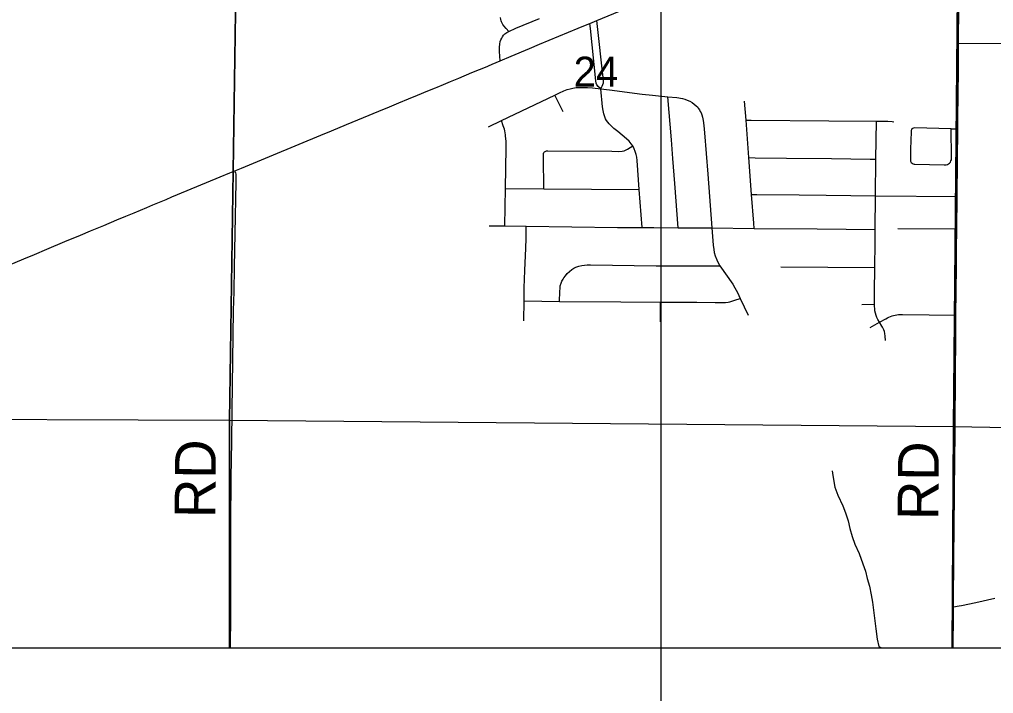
# Model space of a CAD drawing. Extents: x -87 to 2145, y -2128 to 440.
# Drawn here: x -43.13 to -41.77, y -697.486 to -696.545 of the extents above; entities that cross this region are included whole.
import ezdxf

# ---------------------------------------------------------------- set-up
doc = ezdxf.new("R2010")
doc.units = 0
for name, color, linetype in [('GM_X_City_Street', 7, 'Continuous'), ('GM_X_County_Road', 7, 'Continuous'), ('GM_X_County_Road_Text', 7, 'Continuous'), ('GM_X_Minor_River', 7, 'Continuous'), ('GM_X_Section', 7, 'Continuous'), ('GM_X_Section_Text', 7, 'Continuous'), ('GM_X_Township_Road', 7, 'Continuous'), ('GM_X_Township_Road_Text', 7, 'Continuous'), ('GM_X_Township_Text', 7, 'Continuous'), ('SC_Scratch1', 7, 'Continuous'), ('SH_Cut_Line', 7, 'Continuous'), ('SN_P_Text', 7, 'Continuous')]:
    doc.layers.add(name, color=color, linetype=linetype)

msp = doc.modelspace()

# ---------------------------------------------------------------- linework, layer by layer
at = {"layer": 'GM_X_City_Street'}
for p, q in [((-42.3711, -696.6737), (-42.3828, -696.6504)), ((-41.9038, -696.8369), (-41.8215, -696.8373)), ((-42.0671, -696.8902), (-41.9361, -696.8913)), ((-42.2353, -696.9672), (-42.2353, -696.9395)), ((-41.9541, -696.943), (-41.9365, -696.9427))]:
    msp.add_line(p, q, dxfattribs=at)
for points in [[(-42.4589, -696.6025), (-42.4598, -696.5898), (-42.4599, -696.5836), (-42.4597, -696.5793), (-42.4589, -696.5756), (-42.458, -696.5731), (-42.4568, -696.5708), (-42.4558, -696.569), (-42.4543, -696.5669), (-42.4526, -696.5651), (-42.4499, -696.5633), (-42.4471, -696.5617), (-42.4373, -696.5571), (-42.404, -696.5433)], [(-42.4471, -696.5617), (-42.4509, -696.5575), (-42.454, -696.554), (-42.4555, -696.5519), (-42.4564, -696.5501), (-42.4571, -696.5484), (-42.4576, -696.5468), (-42.458, -696.545), (-42.4584, -696.5423)], [(-42.3186, -696.6416), (-42.3167, -696.6382), (-42.3156, -696.6357), (-42.315, -696.6334), (-42.3148, -696.629), (-42.3156, -696.6222), (-42.3233, -696.5549), (-42.3243, -696.5464)], [(-42.3186, -696.6416), (-42.3222, -696.6385), (-42.3242, -696.636), (-42.3251, -696.6339), (-42.3257, -696.6306), (-42.3331, -696.5573), (-42.3338, -696.5504)], [(-41.8194, -696.5782), (-41.7567, -696.5786), (-41.6932, -696.5793), (-41.6298, -696.5803), (-41.5452, -696.581), (-41.4808, -696.5816), (-41.4797, -696.5816), (-41.4131, -696.583), (-41.3978, -696.5833), (-41.319, -696.5825), (-41.3127, -696.5824), (-41.2588, -696.583), (-41.2535, -696.5831), (-41.1875, -696.5837), (-41.1213, -696.5842), (-41.0942, -696.5845), (-41.0122, -696.5851), (-41.0046, -696.5852)], [(-42.4752, -696.6947), (-42.4573, -696.6861), (-42.3828, -696.6504), (-42.3764, -696.6473), (-42.3701, -696.6446), (-42.3654, -696.6429), (-42.3613, -696.6416), (-42.3574, -696.6408), (-42.3528, -696.6401), (-42.3491, -696.6398), (-42.3453, -696.6397), (-42.3372, -696.6397), (-42.3302, -696.6402), (-42.3186, -696.6416), (-42.3066, -696.643), (-42.261, -696.649), (-42.2462, -696.6507), (-42.2248, -696.6527), (-42.2125, -696.654), (-42.2047, -696.6552), (-42.2011, -696.6562), (-42.1981, -696.6574), (-42.1944, -696.6591), (-42.1912, -696.661), (-42.1882, -696.663), (-42.1854, -696.6653), (-42.1837, -696.6671), (-42.1826, -696.6687), (-42.181, -696.671), (-42.1798, -696.6734), (-42.1787, -696.6755), (-42.1776, -696.6781), (-42.1767, -696.6813), (-42.1759, -696.6862), (-42.1749, -696.6931), (-42.1737, -696.7032), (-42.1692, -696.7608), (-42.1634, -696.836), (-42.1616, -696.86), (-42.161, -696.8662), (-42.1602, -696.8705), (-42.1588, -696.8752), (-42.1568, -696.8804), (-42.1544, -696.8855), (-42.1523, -696.8891), (-42.1344, -696.9146), (-42.1313, -696.9196), (-42.1276, -696.9264), (-42.1239, -696.9344), (-42.1128, -696.9579)], [(-42.2608, -696.8353), (-42.2649, -696.7822), (-42.268, -696.7417), (-42.2685, -696.737), (-42.2691, -696.7335), (-42.2704, -696.7294), (-42.2719, -696.7254), (-42.274, -696.7213), (-42.276, -696.7185), (-42.2792, -696.7147), (-42.2827, -696.7114), (-42.2949, -696.7014), (-42.3003, -696.6971), (-42.3042, -696.6935), (-42.3068, -696.6907), (-42.3088, -696.6884), (-42.3104, -696.6861), (-42.3118, -696.6835), (-42.313, -696.6809), (-42.3143, -696.6766), (-42.3154, -696.672), (-42.3161, -696.6669), (-42.3186, -696.6416)], [(-42.2108, -696.8357), (-42.2154, -696.7738), (-42.2179, -696.7391), (-42.2199, -696.7131), (-42.2248, -696.6527)], [(-42.1046, -696.8367), (-42.1051, -696.8294), (-42.1081, -696.7894), (-42.112, -696.7378), (-42.1159, -696.6854), (-42.1179, -696.6592)], [(-42.4523, -696.8333), (-42.4515, -696.7809), (-42.4509, -696.7242), (-42.4509, -696.7149), (-42.4514, -696.708), (-42.4516, -696.7058), (-42.4519, -696.7033), (-42.4525, -696.7005), (-42.453, -696.6981), (-42.4547, -696.6933), (-42.4573, -696.6861)], [(-42.1159, -696.6854), (-42.1087, -696.6854), (-42.0001, -696.6864), (-41.9338, -696.6869), (-41.918, -696.6871), (-41.9119, -696.6875), (-41.9095, -696.6878)], [(-41.9213, -696.9933), (-41.9216, -696.987), (-41.9221, -696.9833), (-41.9228, -696.9807), (-41.9237, -696.9782), (-41.9244, -696.9764), (-41.9253, -696.9747), (-41.9262, -696.9731), (-41.9296, -696.9678), (-41.9317, -696.9641), (-41.9332, -696.9612), (-41.9343, -696.9584), (-41.9353, -696.9552), (-41.9359, -696.9518), (-41.9362, -696.9493), (-41.9364, -696.9448), (-41.9365, -696.9427), (-41.9364, -696.9251), (-41.9361, -696.8913), (-41.9357, -696.8568), (-41.9355, -696.8383), (-41.9351, -696.791), (-41.9345, -696.7399), (-41.9338, -696.6869)], [(-41.8297, -696.6976), (-41.8806, -696.6964), (-41.8823, -696.6966), (-41.8834, -696.697), (-41.8843, -696.6978), (-41.885, -696.6988), (-41.8854, -696.7), (-41.8856, -696.7019), (-41.8863, -696.7261), (-41.8865, -696.741), (-41.8863, -696.7427), (-41.8858, -696.7439), (-41.8852, -696.7448), (-41.8842, -696.7456), (-41.8825, -696.7465), (-41.8814, -696.7468), (-41.8801, -696.747), (-41.8392, -696.7479), (-41.8366, -696.7477), (-41.8349, -696.7474), (-41.8332, -696.7467), (-41.8317, -696.7456), (-41.8306, -696.7442), (-41.8298, -696.7425), (-41.8293, -696.7407), (-41.8292, -696.7376), (-41.8297, -696.6976), (-41.8203, -696.6977)], [(-42.3983, -696.7814), (-42.3987, -696.7375), (-42.3987, -696.7341), (-42.3985, -696.7321), (-42.398, -696.7308), (-42.3972, -696.7298), (-42.3962, -696.7291), (-42.3945, -696.7285), (-42.3926, -696.7282), (-42.3032, -696.729), (-42.2932, -696.7291), (-42.2886, -696.7288), (-42.2859, -696.7283), (-42.2841, -696.7276), (-42.2815, -696.7259), (-42.274, -696.7213)], [(-42.112, -696.7378), (-42.1031, -696.7379), (-42.0593, -696.7384), (-41.9968, -696.7391), (-41.9424, -696.7398), (-41.9345, -696.7399)], [(-42.4515, -696.7809), (-42.3983, -696.7814), (-42.2649, -696.7822)], [(-42.1081, -696.7894), (-42.101, -696.7894), (-42.0415, -696.7899), (-42.0038, -696.7903), (-41.9351, -696.791), (-41.8211, -696.792)], [(-42.4744, -696.833), (-42.4523, -696.8333), (-42.4228, -696.8336), (-42.2954, -696.8352), (-42.2608, -696.8353), (-42.2444, -696.8354), (-42.2108, -696.8357), (-42.1634, -696.836), (-42.1046, -696.8367), (-42.0168, -696.8374), (-41.9355, -696.8383)], [(-42.4259, -696.9659), (-42.4256, -696.9379), (-42.4254, -696.9195), (-42.4246, -696.8957), (-42.4233, -696.8645), (-42.4229, -696.8509), (-42.4229, -696.8422), (-42.4228, -696.8336)], [(-42.376, -696.9386), (-42.3758, -696.9246), (-42.3755, -696.92), (-42.3751, -696.9171), (-42.3741, -696.9133), (-42.3728, -696.9102), (-42.3713, -696.9076), (-42.37, -696.9056), (-42.3679, -696.9028), (-42.3654, -696.8998), (-42.3624, -696.8968), (-42.3592, -696.8943), (-42.3563, -696.8924), (-42.3533, -696.8909), (-42.3492, -696.8895), (-42.3452, -696.8884), (-42.3414, -696.8878), (-42.3377, -696.8875), (-42.3328, -696.8874), (-42.2415, -696.8888), (-42.159, -696.8891), (-42.1523, -696.8891)], [(-42.4256, -696.9379), (-42.376, -696.9386), (-42.2906, -696.9392), (-42.2353, -696.9395), (-42.1844, -696.9398), (-42.1589, -696.9402), (-42.1484, -696.9403), (-42.1447, -696.9401), (-42.1408, -696.9396), (-42.1383, -696.9391), (-42.1313, -696.937), (-42.1239, -696.9344)], [(-41.9424, -696.9752), (-41.9296, -696.9678), (-41.9208, -696.9628), (-41.9184, -696.9615), (-41.9164, -696.9606), (-41.9144, -696.9598), (-41.9121, -696.959), (-41.9102, -696.9584), (-41.9079, -696.9578), (-41.9055, -696.9574), (-41.9031, -696.9571), (-41.9001, -696.9569), (-41.8977, -696.9569), (-41.8229, -696.9577)]]:
    msp.add_lwpolyline(points, dxfattribs=at)
at = {"layer": 'GM_X_County_Road'}
for p, q in [((-41.8194, -696.5892), (-41.8194, -696.5782)), ((-41.8194, -696.616), (-41.8194, -696.5892)), ((-41.8219, -696.8663), (-41.8215, -696.8373)), ((-41.8223, -696.8908), (-41.8219, -696.8663)), ((-41.8229, -696.9577), (-41.8223, -696.8908)), ((-41.8265, -697.3828), (-41.8264, -697.368)), ((-41.8264, -697.368), (-41.8264, -697.365))]:
    msp.add_line(p, q, dxfattribs=at)
for points in [[(-42.3338, -696.5504), (-42.3243, -696.5464), (-42.3002, -696.5365), (-42.2497, -696.5157), (-42.2015, -696.4957), (-42.1755, -696.4849), (-42.1547, -696.4765)], [(-41.8194, -696.5782), (-41.8189, -696.5255), (-41.8188, -696.5101)], [(-42.4589, -696.6025), (-42.4439, -696.596), (-42.4179, -696.5852), (-42.4041, -696.5795), (-42.3501, -696.5572), (-42.3352, -696.5509), (-42.3338, -696.5504)], [(-42.4752, -696.6095), (-42.4703, -696.6074), (-42.4589, -696.6025)], [(-42.5472, -696.6395), (-42.5381, -696.6357), (-42.5284, -696.6317), (-42.5167, -696.6268), (-42.4986, -696.6191), (-42.4877, -696.6147)], [(-42.4877, -696.6147), (-42.4817, -696.6122), (-42.4761, -696.6099), (-42.4752, -696.6095)], [(-41.8215, -696.8373), (-41.8211, -696.792), (-41.8207, -696.7425), (-41.8203, -696.6977), (-41.8202, -696.6828), (-41.8194, -696.616)], [(-42.8293, -696.7562), (-42.8201, -696.7524), (-42.7752, -696.7338), (-42.7092, -696.7065), (-42.6943, -696.7004), (-42.6735, -696.6918), (-42.6499, -696.682), (-42.6286, -696.6731), (-42.6136, -696.6669), (-42.6004, -696.6615), (-42.5869, -696.6558), (-42.5745, -696.6507), (-42.5602, -696.6447), (-42.5491, -696.6402), (-42.5472, -696.6395)], [(-43.2018, -696.9116), (-43.1239, -696.8792), (-43.1092, -696.873), (-43.0918, -696.8656), (-43.0667, -696.8549), (-43.0449, -696.8459), (-43.0307, -696.84), (-43.0124, -696.8324), (-42.9943, -696.8249), (-42.9813, -696.8195), (-42.9699, -696.8147), (-42.961, -696.811), (-42.9521, -696.8073), (-42.9438, -696.8039), (-42.9345, -696.8), (-42.9254, -696.7961), (-42.9172, -696.7927), (-42.9094, -696.7895), (-42.8498, -696.7648), (-42.8364, -696.7591), (-42.8293, -696.7562)], [(-41.823, -696.9911), (-41.823, -696.9901), (-41.8229, -696.9577)], [(-41.8241, -697.1162), (-41.8233, -697.0385), (-41.823, -696.9911)], [(-41.8264, -697.365), (-41.8257, -697.2913), (-41.8254, -697.2596), (-41.8249, -697.2019), (-41.8242, -697.1211), (-41.8241, -697.1162)], [(-41.8268, -697.4226), (-41.8267, -697.4155), (-41.8265, -697.3828)]]:
    msp.add_lwpolyline(points, dxfattribs=at)
at = {"layer": 'GM_X_Minor_River'}
msp.add_lwpolyline([(-41.9956, -697.1752), (-41.9946, -697.1816), (-41.9918, -697.1979), (-41.9879, -697.2094), (-41.9809, -697.2243), (-41.9769, -697.2339), (-41.9733, -697.2453), (-41.9712, -697.2559), (-41.9676, -697.267), (-41.964, -697.2777), (-41.9581, -697.2907), (-41.9527, -697.3052), (-41.949, -697.3155), (-41.9469, -697.3258), (-41.9437, -697.3361), (-41.9412, -697.3486), (-41.9395, -697.3585), (-41.9378, -697.3699), (-41.9365, -697.381), (-41.9348, -697.3958), (-41.9328, -697.4102), (-41.9303, -697.4205), (-41.927, -697.4226)], dxfattribs=at)
at = {"layer": 'GM_X_Section'}
for points in [[(-43.8768, -696.0847), (-42.822, -696.0915), (-42.8367, -697.1048), (-43.8563, -697.1014), (-43.8885, -697.1015)], [(-42.822, -696.0915), (-41.8171, -696.1079), (-41.8263, -697.1137), (-42.8367, -697.1048)], [(-41.8171, -696.1079), (-40.8107, -696.1146), (-40.8081, -697.1324), (-41.8263, -697.1137)]]:
    msp.add_lwpolyline(points, close=True, dxfattribs=at)
at = {"layer": 'GM_X_Township_Road'}
for points in [[(-42.8354, -697.4226), (-42.8351, -697.3769), (-42.8351, -697.3216), (-42.835, -697.2489), (-42.8346, -697.1849), (-42.8338, -697.1345), (-42.8331, -697.091), (-42.8311, -696.9512), (-42.8305, -696.9251), (-42.8298, -696.891), (-42.8288, -696.8437), (-42.8275, -696.772), (-42.8274, -696.7653), (-42.8275, -696.763), (-42.8276, -696.7611), (-42.8282, -696.7591), (-42.8288, -696.7576), (-42.8293, -696.7562)], [(-41.8264, -697.365), (-41.8185, -697.364), (-41.8152, -697.3633), (-41.7951, -697.3592), (-41.7685, -697.353)]]:
    msp.add_lwpolyline(points, dxfattribs=at)
at = {"layer": 'GM_X_Township_Text'}
msp.add_lwpolyline([(-44.882, -697.4226), (-40.5691, -697.4226)], dxfattribs=at)
at = {"layer": 'SC_Scratch1'}
msp.add_line((-42.2347, -696.0462), (-42.2347, -700.1902), dxfattribs=at)
at = {"layer": 'SH_Cut_Line'}
msp.add_lwpolyline([(-47.0365, -692.0677), (-47.0365, -697.4226), (-40.2365, -697.4226), (-40.2365, -692.0607)], dxfattribs=at)
at = {"layer": 'SN_P_Text'}
for points in [[(-43.8567, -697.4226), (-42.8366, -697.4226), (-42.8367, -697.1048), (-43.8563, -697.1014)], [(-42.8366, -697.4226), (-41.8282, -697.4226), (-41.8263, -697.1137), (-42.8367, -697.1048)], [(-41.8282, -697.4226), (-40.812, -697.4226), (-40.8081, -697.1324), (-41.8263, -697.1137)]]:
    msp.add_lwpolyline(points, close=True, dxfattribs=at)

# ---------------------------------------------------------------- texts
at = {"layer": 'GM_X_County_Road_Text'}
msp.add_text('RD', height=0.05682, rotation=89.5055, dxfattribs=at).set_placement((-41.8476, -697.2442))
at = {"layer": 'GM_X_Section_Text'}
msp.add_text('24', height=0.04186, rotation=0, dxfattribs=at).set_placement((-42.3565, -696.6387))
at = {"layer": 'GM_X_Township_Road_Text'}
msp.add_text('RD', height=0.05682, rotation=89.5063, dxfattribs=at).set_placement((-42.8567, -697.2414))

doc.saveas('drawing.dxf')
